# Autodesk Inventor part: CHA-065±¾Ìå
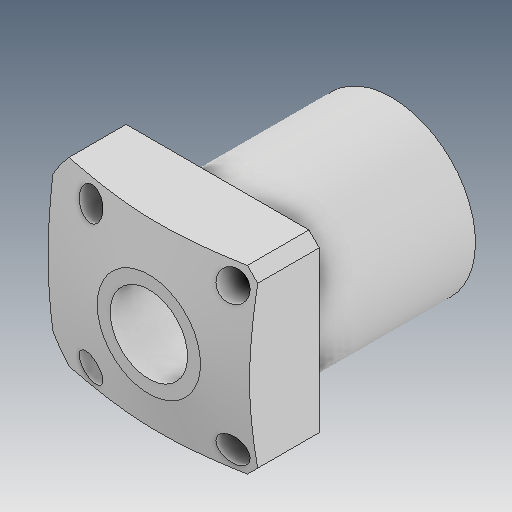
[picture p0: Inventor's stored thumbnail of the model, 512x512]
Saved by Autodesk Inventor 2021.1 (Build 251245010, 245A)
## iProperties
Created: 2019-12
Part Number: CHA-065±¾Ìå
Material: Ogólny
Document SubType Name: Modeling
Designer: user
Density: 1 g/cm^3
Appearance: Domyślna
Author: user
Revision Number: ÈÎºÎ
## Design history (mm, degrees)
feature "ÇÐ³ý-À­Éì7"
node "Bryła1"
